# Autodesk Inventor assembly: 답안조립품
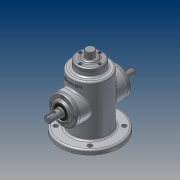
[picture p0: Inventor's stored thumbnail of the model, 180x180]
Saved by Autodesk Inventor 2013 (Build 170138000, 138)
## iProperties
Created: 2014-12
Part Number: 답안조립품
Document SubType Name: Assembly
Designer: SD
Author: SD
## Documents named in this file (12)
- C:\Users\CAD-B25\Desktop\441228V1009\답안조립품.iam
- C:\Users\CAD-B25\Desktop\441228V1009\본체.ipt
- C:\Users\CAD-B25\Desktop\441228V1009\M3x0.5x8.ipt
- M3x0.5.ipt
- C:\Users\CAD-B25\Desktop\441228V1009\베어링 6002.ipt
- 베어링 6002.ipt
- C:\Users\CAD-B25\Desktop\441228V1009\상단커버.ipt
- C:\Users\CAD-B25\Desktop\441228V1009\슬라이드.ipt
- C:\Users\CAD-B25\Desktop\441228V1009\오일실.ipt
- 오일실.ipt
- C:\Users\CAD-B25\Desktop\441228V1009\커버.ipt
- C:\Users\CAD-B25\Desktop\441228V1009\편심축.ipt
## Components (12 placed, 1 different names)
1. M3x0.5:1 — 각도:2
2. M3x0.5:4
3. M3x0.5:5
4. M3x0.5:6
5. M3x0.5:3 — 각도:3
6. M3x0.5:7
7. M3x0.5:8
8. M3x0.5:9
9. M3x0.5:2 — 각도:4
10. M3x0.5:10
11. M3x0.5:11
12. M3x0.5:12
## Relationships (3: Angle 3)
- 각도:2 [Angle]: M3x0.5:1
- 각도:3 [Angle]: M3x0.5:3
- 각도:4 [Angle]: M3x0.5:2
